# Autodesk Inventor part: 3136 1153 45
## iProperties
Shininess: 60.0
Length Units: 11269
Angle Units: 11279
Time Units: 11290
Mass Units: 11283
Length Display Precision: 3
Angle Display Precision: 2
Compacted: True
Created: 2000-11
Part Number: 3136 1153 45
Material: Steel, Mild
Description: Plate
Document SubType Name: Sheet Metal
Designer: Joe M
Engineer: Joe M
Density: 7.86
Volumn: 449.24575811314656
Area: 1873.8428019340934
PropertySet Name: Model Information
Control State: 0
Master: False
Checked Out: False
Last Check In By: brjdn
Last Check In Date: 2002-01-08
Title: Underplåt
Author: Joe M
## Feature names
1. Extrusion5
2. Extrusion7
3. Corner Round1
4. Corner Round3
5. FlatPatternExtrusion1
6. Cut1
